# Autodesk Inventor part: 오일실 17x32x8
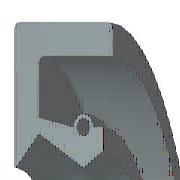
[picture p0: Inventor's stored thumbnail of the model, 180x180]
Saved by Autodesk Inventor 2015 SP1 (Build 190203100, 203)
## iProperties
IsCustomPart: 1
Company: 한국ATC센터
Created: 2014-07
Part Number: 오일실 17x32x8
Material: 고무
Description: 오일-실
Document SubType Name: Modeling
Standard: KS B 2804
Designer: KYOUNG IL JANG
Standards Organization: KS
Language: ko-KR
Size Designation: D - 17 32 8
Categories: <MemberInstance><Categories><Category DisplayName="샤프트 부품" InternalName="7f7aeb1f-a693-4053-b835-cee3144e0d98" Mnemonic="SHFT"><Category DisplayName="실링" Intern
Density: 0.93 g/cm^3
Appearance: 고무 - 검은색 - 버전 1.1
Author: KYOUNG IL JANG
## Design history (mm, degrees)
revolve "본체" stored, may be unused: angle "d17" = 90 deg
revolve "스프링1" stored, may be unused: angle "d18" = 90 deg
body "Solid1"
sketch "스케치1"
  geometry: L1 (0, 16)-(8, 16); L2 (8, 14.25)-(1.75, 14.25); L3 (1.75, 10.25)-(4.9, 8.5); L4 (4.9, 8.5)-(0, 8.5); L5 (0, 0)-(9.586, 0) reference; L6 (4.9, 8.5)-(6.3, 9.375); L7 (0, 18)-(0, -3) reference; L8 (-1.941, 0)-(11.507, 0) reference; L9 (4.2, 10.6)-(1.75, 11.21); L10 (1.75, 11.21)-(1.75, 14.25); L11 (0, 16)-(0, 8.588); L12 (4.9, 8.5)-(0, 8.5); L13 (1.75, 10.25)-(0.152, 8.528); L14 (8, 16)-(8, 14.25); L15 (5.6, 10.6)-(6.3, 10.6); L16 (6.3, 10.6)-(6.3, 9.375); C1 r 0.455 at (4.9, 10.6); A1 r 0.7 centre (4.9, 10.6) between (5.6, 10.6) and (4.2, 10.6); A2 r 0.088 centre (0.088, 8.588) between (0, 8.588) and (0.152, 8.528); 1 further point
  constraints: 28 end point, 5 horizontal alignment, 5 point on line, 4 point on circle, 4 vertical alignment, 3 centre point, 3 tangent, 2 collinear, 2 horizontal, 2 perpendicular, 1 coincident, 1 parallel
  dimensions: "d0" = 32 diameter of L1 L5 (= SD2); "d1" = 1.75 distance of L1.end L2.start (= SD); "d2" = 0.91 diameter of C1 (= SPDI); "d3" = 1.4 diameter of A1 (= SPDA); "d4" = 17 diameter of L3.end L5 (= NND); "d5" = 20.5 diameter of L3.start L5 (= TKDM); "d7" = 22.42 diameter of L9.end L5 (= TKDM + 0.24 x SWDT); "d8" = 1.75 distance between parallel lines of L11 L10 (= SD); "d9" = 4.9 distance from line of L11 C1.centre (= SPDST); "d10" = 21.2 diameter of C1.centre L5 (= HLDM); "d11" = 0.0875 radius of A2 (= 0.25 x LAB); "d12" = 6.3 distance between parallel lines of L11 L16 (= SDI); "d13" = 18.75 diameter of L6.end L5 (= ABDM); "d14" = 8 distance from line of L11 L1.end (= SWDT)
fillet "모깎기1" dims "d6" = 0.3 (= RR)
other parameters: "SD2" = 32 [user parameter; used in 1 equation term], "SWDT" = 8 [user parameter; used in 2 equation terms], "RR" = 0.3 [user parameter; used in 1 equation term], "SD" = 1.75 [user parameter; used in 2 equation terms], "NND" = 17 [user parameter; used in 1 equation term], "SPDA" = 1.4 [user parameter; used in 1 equation term], "SPDI" = 0.91 [user parameter; used in 1 equation term], "TKDM" = 20.5 [user parameter; used in 2 equation terms], "HLDM" = 21.2 [user parameter; used in 1 equation term], "ABDM" = 18.75 [user parameter; used in 1 equation term], "SDI" = 6.3 [user parameter; used in 1 equation term], "SPDST" = 4.9 [user parameter; used in 1 equation term], "LAB" = 0.35 [user parameter; used in 1 equation term], "d15" = 0, "d16" = 0, "d19" = 0
